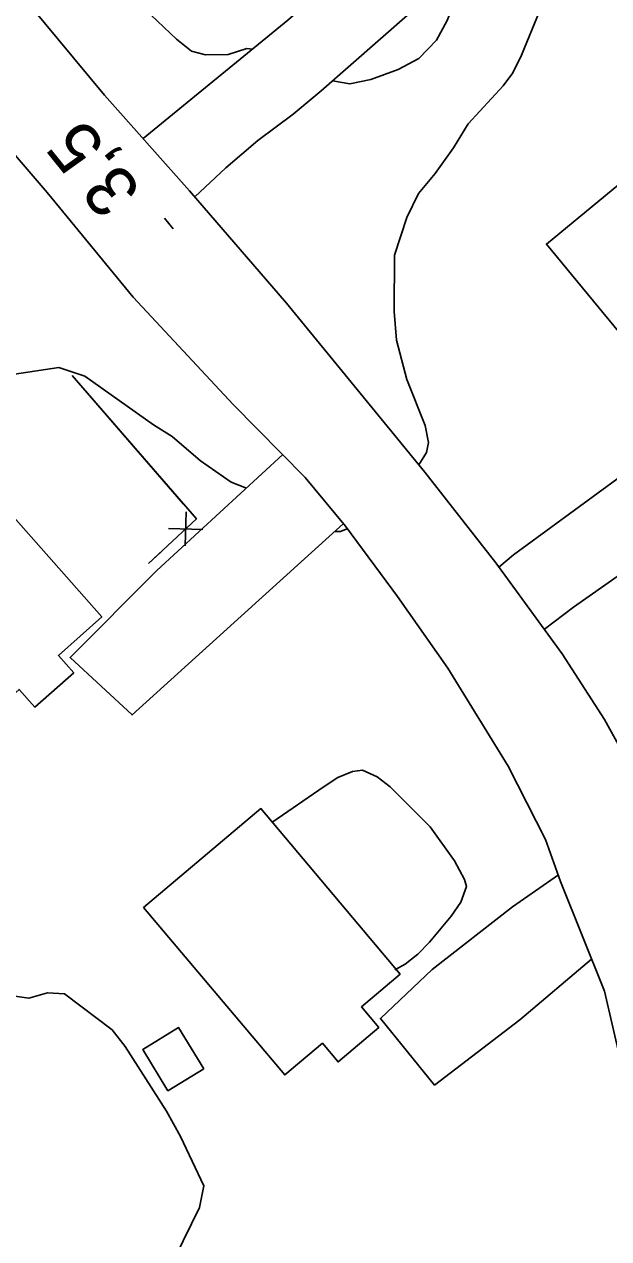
# Model space of a CAD drawing. Extents: x 282461 to 284471, y 5554090 to 5557646.
# Drawn here: x 283239.8 to 283274.2, y 5555396.4 to 5555467.7 of the extents above; entities that cross this region are included whole.
import ezdxf

# ---------------------------------------------------------------- set-up
doc = ezdxf.new("R2010")
doc.units = 0
for name, color, linetype in [('Niveau 1', 7, 'Continuous'), ('Niveau 19', 7, 'Continuous'), ('Niveau 2', 7, 'Continuous'), ('Niveau 21', 7, 'Continuous'), ('Niveau 3', 7, 'Continuous'), ('Niveau 31', 7, 'Continuous'), ('Niveau 37', 7, 'Continuous')]:
    doc.layers.add(name, color=color, linetype=linetype)

msp = doc.modelspace()

# ---------------------------------------------------------------- linework, layer by layer
at = {"layer": 'Niveau 1'}
for points in [[(283263.67, 5555420.62), (283261.33, 5555422.97), (283260.56, 5555423.54), (283259.69, 5555423.93), (283259.11, 5555423.87), (283258.25, 5555423.51), (283257.44, 5555422.98), (283254.37, 5555420.86)], [(283261.6, 5555412.21), (283262.2, 5555412.55), (283262.95, 5555413.13), (283263.64, 5555413.84), (283264.9, 5555415.36), (283265.47, 5555416.18), (283265.8, 5555417.11), (283265.68, 5555417.51), (283265.09, 5555418.61), (283263.67, 5555420.62)]]:
    msp.add_lwpolyline(points, dxfattribs=at)
at = {"layer": 'Niveau 19'}
for points in [[(283246.81, 5555461.03), (283255.31, 5555467.99), (283257.61, 5555469.99), (283259.56, 5555471.93), (283262.5, 5555468.42), (283257.28, 5555463.83), (283255.62, 5555462.46), (283253.56, 5555460.91), (283251.67, 5555459.32), (283249.85, 5555457.6)], [(283267.71, 5555435.87), (283268.57, 5555436.59), (283280.11, 5555445.05), (283282.89, 5555440.91), (283279.26, 5555438.55), (283272.08, 5555433.52), (283270.38, 5555432.21)], [(283255.02, 5555442.47), (283247.63, 5555435.66), (283242.53, 5555430.56), (283246.17, 5555427.18), (283258.57, 5555438.41)], [(283271.2, 5555417.79), (283268.51, 5555415.92), (283263.79, 5555412.23), (283260.75, 5555409.36), (283263.93, 5555405.45), (283268.93, 5555409.28), (283273.15, 5555412.84)]]:
    msp.add_lwpolyline(points, dxfattribs=at)
at = {"layer": 'Niveau 2'}
for points in [[(283257.94, 5555464.41), (283258.96, 5555464.25), (283260.18, 5555464.49), (283261.8, 5555465.09), (283263.01, 5555465.74), (283264.04, 5555466.8), (283264.67, 5555467.97), (283265.23, 5555469.37), (283265.56, 5555470.53), (283266.59, 5555476.81), (283266.57, 5555478.78), (283266.31, 5555481.39), (283264.78, 5555482.65), (283263.96, 5555483.51), (283262.49, 5555484.59), (283258.76, 5555486.06), (283257.77, 5555486.28), (283256.73, 5555486.23)], [(283253.26, 5555485.16), (283251.82, 5555484.41), (283250.03, 5555483.63), (283246.27, 5555482.66), (283244.54, 5555481.89), (283242.98, 5555480.71), (283242.13, 5555479.25), (283241.86, 5555477.22), (283242.06, 5555475.77), (283242.54, 5555474.32), (283243.48, 5555472.71), (283244.13, 5555471.79), (283246.55, 5555468.98), (283248.78, 5555466.86), (283249.66, 5555466.17), (283250.47, 5555465.95), (283251.81, 5555465.96)], [(283274.18, 5555473.01), (283272.81, 5555471.43), (283271.72, 5555470.37), (283270.11, 5555468.55), (283269.04, 5555465.93), (283268.53, 5555464.88), (283267.96, 5555464.12), (283265.9, 5555461.89), (283265.05, 5555460.49), (283263.96, 5555458.97), (283262.99, 5555457.8), (283262.31, 5555456.4), (283261.58, 5555454.18), (283261.56, 5555450.88), (283261.7, 5555449.2), (283262.31, 5555446.88), (283263.38, 5555444.17), (283263.57, 5555443.19), (283263.46, 5555442.6), (283263, 5555441.87)], [(283251.81, 5555465.96), (283252.9, 5555466.32), (283253.21, 5555466.27)], [(283252.89, 5555440.5), (283251.99, 5555440.85), (283250.18, 5555442.1), (283248.53, 5555443.54), (283247.42, 5555444.22), (283243.39, 5555447.07), (283241.87, 5555447.58), (283239.26, 5555447.2)], [(283258.83, 5555438.13), (283258.41, 5555437.96), (283258.07, 5555437.96)], [(283238.6, 5555410.77), (283240.11, 5555410.55), (283241.21, 5555410.86), (283242.19, 5555410.81), (283245, 5555408.69), (283245.77, 5555407.72), (283248.19, 5555403.92), (283249.02, 5555402.42), (283250.39, 5555399.53), (283250.12, 5555398.26), (283248.7, 5555395.34)]]:
    msp.add_lwpolyline(points, dxfattribs=at)
at = {"layer": 'Niveau 21'}
for points in [[(283274.88, 5555406.74), (283273.9, 5555410.96), (283271.33, 5555417.41), (283270.44, 5555419.87), (283268.25, 5555424.18), (283264.71, 5555429.93), (283261.75, 5555434.13), (283258.69, 5555438.26), (283256.34, 5555441.13), (283252.11, 5555445.42), (283246.24, 5555451.72), (283241.18, 5555457.86), (283233.89, 5555466.34), (283224.23, 5555478.24), (283219.69, 5555483.52), (283211.09, 5555494.09), (283204.97, 5555500.94), (283194.85, 5555512.7), (283188.06, 5555522.14), (283183.69, 5555527.84), (283179.15, 5555533.53), (283174.62, 5555538.99), (283170.27, 5555543.29)], [(283181.21, 5555541.86), (283191, 5555529.22), (283194.93, 5555524.39), (283198.1, 5555520.26), (283200.8, 5555516.52), (283207.7, 5555507.6), (283212.23, 5555502.05), (283219.26, 5555493.78), (283224.18, 5555487.65), (283229.04, 5555481.82), (283238.3, 5555471.1), (283244.54, 5555463.58), (283249.54, 5555457.96), (283255.24, 5555451.36), (283263.36, 5555441.44), (283267.53, 5555436.11), (283271.42, 5555430.77), (283273.9, 5555426.92), (283276.92, 5555421.46)]]:
    msp.add_lwpolyline(points, dxfattribs=at)
at = {"layer": 'Niveau 3'}
msp.add_line((283248.58, 5555455.73), (283248.07, 5555456.35), dxfattribs=at)
at = {"layer": 'Niveau 31'}
for points in [[(283278.68, 5555444.9), (283270.5, 5555454.83), (283277.44, 5555460.55), (283285.64, 5555450.6), (283283.65, 5555448.96), (283284.67, 5555447.72), (283282.25, 5555445.73), (283281.23, 5555446.98), (283278.68, 5555444.9)], [(283235.92, 5555442.51), (283244.39, 5555432.94), (283241.84, 5555430.68), (283242.74, 5555429.66), (283240.46, 5555427.64), (283239.53, 5555428.68), (283237.46, 5555426.84), (283229.01, 5555436.4), (283235.92, 5555442.51)], [(283246.84, 5555415.88), (283253.73, 5555421.68), (283261.9, 5555411.96), (283259.63, 5555410.04), (283260.65, 5555408.83), (283258.26, 5555406.81), (283257.34, 5555407.9), (283255.13, 5555406.04), (283246.84, 5555415.88)], [(283250.38, 5555406.4), (283248.9, 5555408.82), (283246.79, 5555407.53), (283248.27, 5555405.11), (283250.38, 5555406.4)]]:
    msp.add_lwpolyline(points, dxfattribs=at)
at = {"layer": 'Niveau 37'}
for p, q in [((283249.35, 5555439.11), (283249.28, 5555437.11)), ((283248.31, 5555438.14), (283250.32, 5555438.07))]:
    msp.add_line(p, q, dxfattribs=at)
for points in [[(283242.65, 5555447.12), (283249.94, 5555438.69), (283247.14, 5555436.08)], [(283242.65, 5555447.12), (283249.19, 5555439.56)], [(283247.85, 5555436.74), (283247.14, 5555436.08)]]:
    msp.add_lwpolyline(points, dxfattribs=at)

# ---------------------------------------------------------------- texts
at = {"layer": 'Niveau 3'}
msp.add_text('3,5  ', height=3, rotation=128.86592, dxfattribs=at).set_placement((283246.8, 5555457.99))

doc.saveas('drawing.dxf')
